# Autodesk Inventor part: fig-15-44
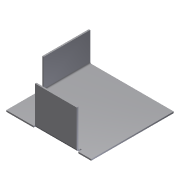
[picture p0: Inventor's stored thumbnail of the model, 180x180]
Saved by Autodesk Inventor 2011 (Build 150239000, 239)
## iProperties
Created: 2005-03
Part Number: fig-15-44
Document SubType Name: Sheet Metal
Designer: CADCIM
Manufacturer: Standard
Standards Organization: Custom
Density: 1 g/cm^3
Sheet Metal Rule: Default
Author: CADCIM
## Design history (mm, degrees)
node "Face1"
  sketch "Sketch1"
    geometry: L1 (-29, -26)-(30, -26); L2 (30, -26)-(30, 31.375); L3 (30, 31.375)-(-29, 31.375); L4 (-29, 31.375)-(-29, -26)
    constraints: 8 end point, 2 parallel, 1 horizontal, 1 perpendicular
node "Flange1"
node "Flange2"
body "Solid1"
face "Plate1" dims "Thickness" = 1
sketch "Sketch2"
  geometry: L1 (25, 0)-(57.375, 0); L2 (57.375, 0)-(57.375, 20); L3 (57.375, 20)-(25, 20); L4 (25, 20)-(25, 0)
  constraints: 8 end point
face "Plate2" dims "d1" = 0, "d2" = 25, "d3" = 1 (= BendReliefWidth), "d5" = 2 (= MinimumRemnant), "d7" = 20, "d8" = 90 deg, "d9" = 1 (= BendRadius), "Thickness" = 1
bend "Bend1" dims "d3" = 1 (= BendReliefWidth), "d4" = 0.5 (= BendReliefDepth), "d5" = 2 (= MinimumRemnant), "d6" = 1 (= BendRadius), "d7" = 20, "d8" = 90 deg, "d9" = 1 (= BendRadius), "SeamGap" = 0.01, "Thickness" = 1
sketch "Sketch3"
  geometry: L1 (10, 0)-(39, 0); L2 (39, 0)-(39, 26); L3 (39, 26)-(10, 26); L4 (10, 26)-(10, 0)
  constraints: 8 end point
face "Plate3" dims "d10" = 20, "d11" = 10, "d12" = 1 (= BendReliefWidth), "d14" = 2 (= MinimumRemnant), "d16" = 26, "d17" = 90 deg, "d18" = 1 (= BendRadius), "Thickness" = 1
bend "Bend2" dims "d12" = 1 (= BendReliefWidth), "d13" = 0.5 (= BendReliefDepth), "d14" = 2 (= MinimumRemnant), "d15" = 1 (= BendRadius), "d16" = 26, "d17" = 90 deg, "d18" = 1 (= BendRadius), "SeamGap" = 0.01, "Thickness" = 1
other parameters: "BendRadius" = 1 (= Thickness), "BendReliefWidth" = 1 (= Thickness), "BendReliefDepth" = 0.5 (= 0.5 x Thickness), "CornerReliefSize" = 4 (= 4 x Thickness), "MinimumRemnant" = 2 (= 2 x Thickness), "TransitionRadius" = 1 (= BendRadius), "d0" = 1 (= BendRadius), "JacobiRadiusSize" = 1 (= Thickness), "GapSize" = 1 (= Thickness)
